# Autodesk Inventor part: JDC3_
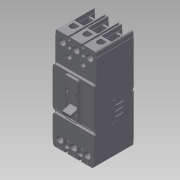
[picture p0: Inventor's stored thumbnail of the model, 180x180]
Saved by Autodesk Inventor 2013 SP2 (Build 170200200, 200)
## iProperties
Created: 2014-08
Part Number: JDC3_
Material: Generic
Document SubType Name: Modeling
Designer: DM/JS
Density: 1 g/cm^3
Description: TYPE JDC THERMAL MAGNETIC CIRCUIT BREAKERS THREE POLE, SERIES C
MXEDIT: false
MXINVTNRV: INV Versioned Component|JDC3_|004.0
Author: DM/JS
Revision Number: 004
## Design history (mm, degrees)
derived "JD3_.iam"
node "L1"
node "L2"
node "L3"
node "T1"
node "T2"
node "T3"
sketch "Sketch1"
  geometry: C1 r 10.795 at (-30.321, -7.974) reference; C2 r 10.795 at (4.604, -7.974) reference; C3 r 10.795 at (39.529, -7.974) reference; C4 r 7.992 at (39.567, -219.912) reference; C5 r 7.992 at (4.616, -219.912) reference; C6 r 7.992 at (-30.334, -219.912) reference; C7 r 10.795 at (-30.321, -7.974); C8 r 10.795 at (4.604, -7.974); C9 r 10.795 at (39.529, -7.974); C10 r 7.992 at (-30.334, -219.912); C11 r 7.992 at (4.616, -219.912); C12 r 7.992 at (39.567, -219.912); 1 further point
  constraints: 6 centre point, 6 coincident, 6 concentric
extrude "Extrusion1" sketch "Sketch1" stored distance "d1" = 25.4; taper "d2" = 0 deg
sketch "Sketch2"
  geometry: L1 (-17.45, 0)-(-34.925, 0) reference; L2 (-34.925, 0)-(-34.925, -23.069) reference; L3 (-34.925, -23.069)-(-17.45, -23.069) reference; L4 (-17.45, -23.069)-(-17.45, 0) reference; L5 (-30.353, -8.794)-(-30.353, -11.969) reference; L6 (-22.022, -11.969)-(-22.022, -8.794) reference; L7 (17.475, 0)-(0, 0) reference; L8 (0, 0)-(0, -23.069) reference; L9 (0, -23.069)-(17.475, -23.069) reference; L10 (17.475, -23.069)-(17.475, 0) reference; L11 (4.572, -8.794)-(4.572, -11.969) reference; L12 (12.903, -11.969)-(12.903, -8.794) reference; L13 (52.4, 0)-(34.925, 0) reference; L14 (34.925, 0)-(34.925, -23.069) reference; L15 (34.925, -23.069)-(52.4, -23.069) reference; L16 (52.4, -23.069)-(52.4, 0) reference; L17 (39.497, -8.794)-(39.497, -11.969) reference; L18 (47.828, -11.969)-(47.828, -8.794) reference; A1 r 4.166 centre (-26.187, -8.794) between (-22.022, -8.794) and (-30.353, -8.794) reference; A2 r 4.166 centre (-26.187, -11.969) between (-30.353, -11.969) and (-22.022, -11.969) reference; A3 r 4.166 centre (8.738, -8.794) between (12.903, -8.794) and (4.572, -8.794) reference; A4 r 4.166 centre (8.738, -11.969) between (4.572, -11.969) and (12.903, -11.969) reference; A5 r 4.166 centre (43.663, -8.794) between (47.828, -8.794) and (39.497, -8.794) reference; A6 r 4.166 centre (43.663, -11.969) between (39.497, -11.969) and (47.828, -11.969) reference; 1 further point
extrude "Extrusion2" join sketch "Sketch2" stored distance "d3" = 25.4; taper "d4" = 0 deg
body "Solid1"
node "JD3_.ipt:1"
node "Projected Loop1"
node "Projected Loop2"
node "Projected Loop3"
